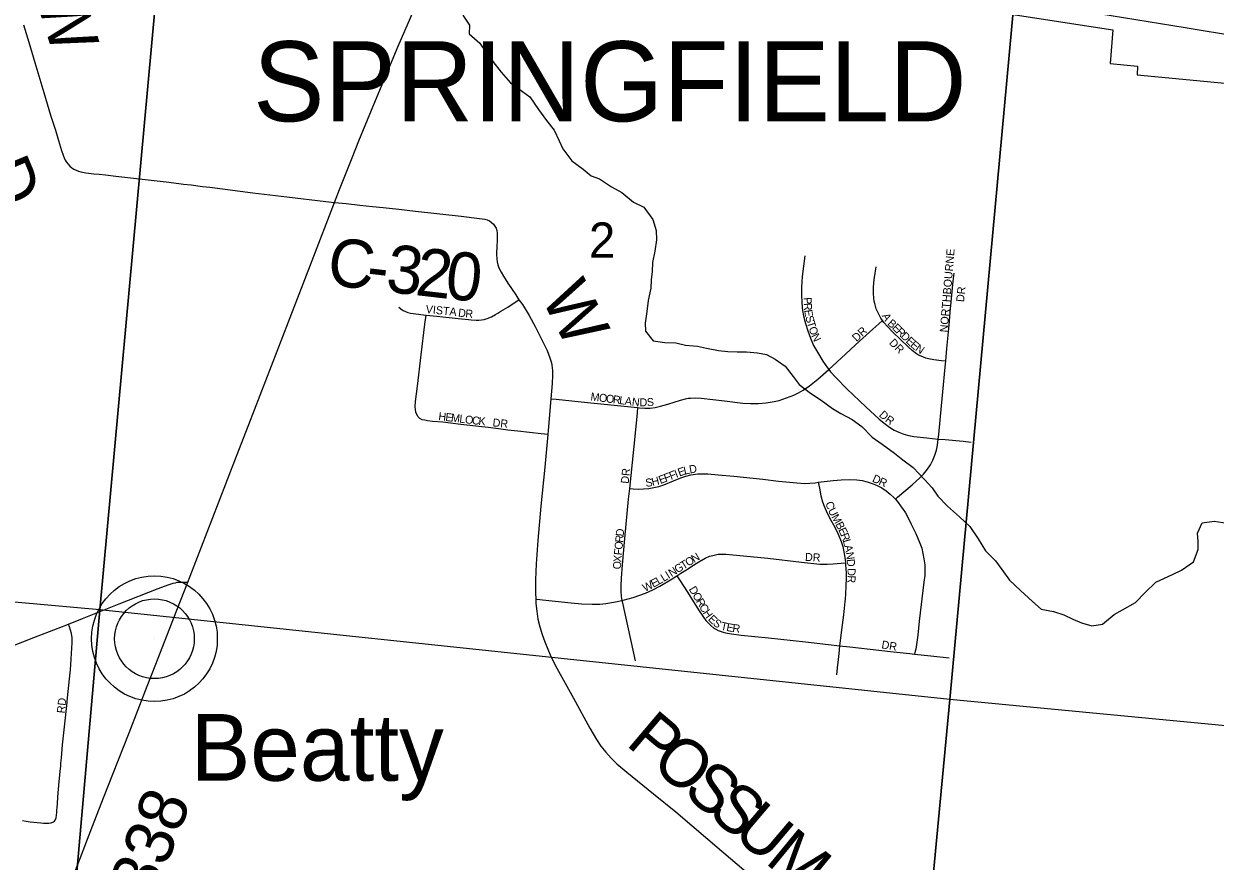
# Model space of a CAD drawing. Extents: x -209 to 4852, y 0 to 905.
# Drawn here: x 81.27 to 109.47, y 211.09 to 230.91 of the extents above; entities that cross this region are included whole.
import ezdxf

# ---------------------------------------------------------------- set-up
doc = ezdxf.new("R2010")
doc.units = 0
for name, color, linetype in [('GM_P_County_Alignment', 7, 'Continuous'), ('GM_X_Corporation_Text', 7, 'Continuous'), ('GM_X_County_Road', 7, 'Continuous'), ('GM_X_County_Road_Text', 7, 'Continuous'), ('GM_X_County_ROW', 7, 'Continuous'), ('GM_X_County_Subdivision', 7, 'Continuous'), ('GM_X_Interstate_Location', 7, 'Continuous'), ('GM_X_Minor_River', 7, 'Continuous'), ('GM_X_Rail_Line_Text', 7, 'Continuous'), ('GM_X_Township_Road', 7, 'Continuous'), ('GM_X_Township_Road_Text', 7, 'Continuous'), ('GM_X_Township_Subdivision_Text', 7, 'Continuous'), ('GM_X_Township_Text', 7, 'Continuous'), ('GM_X_Unincorporated_Location', 7, 'Continuous'), ('GM_X_US_Location', 7, 'Continuous')]:
    doc.layers.add(name, color=color, linetype=linetype)

msp = doc.modelspace()

# ---------------------------------------------------------------- linework, layer by layer
at = {"layer": 'GM_X_County_Road'}
for points in [[(91.656, 231.11), (91.813, 230.874), (91.811, 230.669), (92.059, 230.448), (92.209, 230.227), (92.366, 230.013), (92.568, 229.761), (92.786, 229.51), (92.982, 229.372), (93.245, 229.18), (93.447, 228.883), (93.642, 228.616), (93.822, 228.387), (93.941, 228.136), (94.023, 227.946), (94.24, 227.664), (94.503, 227.465), (94.699, 227.311), (94.895, 227.242), (95.174, 227.05), (95.422, 226.919), (95.7, 226.69), (95.942, 226.567), (96.159, 226.277), (96.233, 226.019), (96.246, 225.799), (96.206, 225.526), (96.151, 225.261), (96.142, 225.049), (96.118, 224.852), (96.109, 224.655), (96.046, 224.359), (96.014, 224.102), (95.974, 223.822), (95.98, 223.632), (96.16, 223.403), (96.44, 223.363), (96.697, 223.354), (96.931, 223.306), (97.211, 223.281), (97.422, 223.234), (97.709, 223.179), (97.929, 223.155), (98.155, 223.145), (98.375, 223.144), (98.632, 223.119), (98.843, 223.08), (99.055, 222.972), (99.288, 222.803), (99.475, 222.559), (99.617, 222.368), (99.888, 222.169), (100.137, 222.001), (100.408, 221.801), (100.603, 221.686), (100.875, 221.54), (101.1, 221.379), (101.348, 221.127), (101.581, 220.958), (101.875, 220.744), (102.071, 220.591), (102.319, 220.407), (102.589, 220.124), (102.769, 219.926), (102.904, 219.727), (103.129, 219.491), (103.415, 219.238), (103.655, 219.009), (103.857, 218.719), (104.029, 218.437), (104.269, 218.2), (104.419, 217.994), (104.599, 217.743), (104.854, 217.498), (105.14, 217.238), (105.35, 217.055), (105.637, 216.999), (105.886, 216.921), (106.097, 216.821), (106.301, 216.729), (106.55, 216.658), (106.8, 216.702), (107.074, 216.927), (107.272, 217.04), (107.576, 217.212), (107.797, 217.445), (108.063, 217.693), (108.458, 217.872), (108.671, 217.976), (108.952, 218.179), (109.06, 218.466), (109.062, 218.656)], [(109.062, 218.656), (109.048, 218.853), (109.156, 219.102), (109.444, 219.138), (109.746, 219.09)]]:
    msp.add_lwpolyline(points, dxfattribs=at)
at = {"layer": 'GM_X_County_Road_Text'}
for points in [[(88.622, 226.679), (88.739, 226.985), (89.036, 227.735), (89.196, 228.14), (89.549, 229.001), (90.127, 230.375), (90.498, 231.229), (90.839, 232.036)], [(85.148, 217.695), (85.202, 217.835), (85.874, 219.572), (86.299, 220.673), (86.59, 221.426), (86.862, 222.119), (87.128, 222.815), (87.535, 223.856), (88.095, 225.304), (88.622, 226.679)], [(88.622, 226.679), (88.898, 226.653), (89.223, 226.618), (89.37, 226.602), (89.521, 226.586), (89.771, 226.559), (90.141, 226.519), (90.538, 226.476), (91.62, 226.352), (92.057, 226.302), (92.178, 226.282), (92.235, 226.265), (92.29, 226.241), (92.339, 226.209), (92.381, 226.169), (92.417, 226.122), (92.444, 226.07), (92.461, 226.013), (92.471, 225.954), (92.473, 225.894), (92.473, 225.772), (92.466, 225.648), (92.459, 225.461), (92.463, 225.335), (92.47, 225.272), (92.487, 225.204), (92.511, 225.136), (92.565, 225.029), (92.618, 224.935), (92.725, 224.772), (92.83, 224.617), (92.914, 224.494), (92.988, 224.379)], [(92.988, 224.379), (93.07, 224.265), (93.133, 224.161), (93.228, 224.004), (93.377, 223.732), (93.547, 223.401), (93.653, 223.177), (93.721, 223.005), (93.755, 222.887), (93.767, 222.828), (93.781, 222.706), (93.782, 222.583), (93.771, 222.398), (93.74, 222.035)], [(93.74, 222.035), (93.676, 221.283), (93.667, 221.187)], [(93.667, 221.187), (93.596, 220.417), (93.505, 219.489), (93.434, 218.683), (93.396, 218.126), (93.38, 217.753), (93.38, 217.441), (93.385, 217.291)], [(80.77, 206.794), (80.798, 206.83), (80.903, 206.982), (80.997, 207.141), (81.082, 207.306), (81.181, 207.532), (81.386, 208.052), (81.809, 209.128), (82.139, 209.965), (82.612, 211.181), (82.879, 211.877), (83.172, 212.629), (83.375, 213.149), (83.761, 214.132), (84.191, 215.23), (84.393, 215.751), (84.821, 216.851), (85.148, 217.695)], [(82.327, 216.704), (82.66, 216.835), (83.527, 217.178), (84.451, 217.547), (84.681, 217.635), (84.799, 217.67), (84.855, 217.682), (84.9, 217.691), (84.942, 217.695), (84.993, 217.695), (85.106, 217.695), (85.148, 217.695)], [(93.385, 217.291), (93.388, 217.191), (93.407, 217.005), (93.437, 216.82), (93.479, 216.637), (93.534, 216.457), (93.597, 216.281), (93.667, 216.107), (93.743, 215.937), (93.886, 215.66), (94.276, 214.952), (94.665, 214.243), (94.824, 213.975), (94.927, 213.817), (95.041, 213.668), (95.167, 213.529), (95.302, 213.399), (95.539, 213.196), (96.168, 212.688), (96.698, 212.256), (97.835, 211.289), (99.258, 210.083)], [(80.282, 215.906), (80.594, 216.03), (80.982, 216.181), (81.505, 216.381), (82.082, 216.608), (82.327, 216.704)]]:
    msp.add_lwpolyline(points, dxfattribs=at)
at = {"layer": 'GM_X_County_ROW'}
msp.add_lwpolyline([(81.259, 230.886), (81.383, 230.469), (81.528, 229.994), (81.744, 229.279), (81.903, 228.743), (82.014, 228.387), (82.088, 228.149), (82.157, 227.911), (82.198, 227.795), (82.221, 227.738), (82.248, 227.684), (82.278, 227.631), (82.314, 227.583), (82.354, 227.539), (82.402, 227.5), (82.45, 227.467), (82.503, 227.44), (82.56, 227.419), (82.618, 227.403), (82.738, 227.381), (82.861, 227.368), (82.924, 227.361), (83.048, 227.347), (83.205, 227.33), (83.445, 227.303), (83.66, 227.279), (83.795, 227.264), (84.211, 227.218), (84.638, 227.168), (84.939, 227.129), (85.05, 227.115), (85.227, 227.093), (85.499, 227.059), (85.667, 227.038), (86.689, 226.91), (87.491, 226.811), (88.417, 226.7), (88.622, 226.679)], dxfattribs=at)
at = {"layer": 'GM_X_County_Subdivision'}
msp.add_line((84.36, 216.356), (84.36, 216.356), dxfattribs=at)
at = {"layer": 'GM_X_Minor_River'}
for points in [[(65.048, 238.898), (84.904, 237.096), (83.068, 217.043), (63.212, 218.824)], [(84.904, 237.096), (105.036, 235.054), (103.184, 214.918), (83.068, 217.043)], [(105.036, 235.054), (125.307, 233.161), (123.431, 212.988), (103.184, 214.918)], [(61.756, 202.559), (81.8, 202.559), (83.068, 217.043), (63.212, 218.824)], [(81.8, 202.559), (102.019, 202.559), (103.184, 214.918), (83.068, 217.043)], [(102.019, 202.559), (122.379, 202.559), (123.431, 212.988), (103.184, 214.918)]]:
    msp.add_lwpolyline(points, close=True, dxfattribs=at)
at = {"layer": 'GM_X_Rail_Line_Text'}
msp.add_lwpolyline([(95.901, 232.909), (99.91, 232.247), (102.8, 231.787), (107, 231.106), (108.753, 230.822), (109.994, 230.618), (112.682, 230.182)], dxfattribs=at)
at = {"layer": 'GM_X_Township_Subdivision_Text'}
for radius in [1.488, 0.943]:
    msp.add_circle((84.36, 216.356), radius, dxfattribs=at)
at = {"layer": 'GM_X_Township_Text'}
for points in [[(99.75, 225.416), (99.692, 224.924), (99.673, 224.676), (99.671, 224.491), (99.681, 224.305), (99.7, 224.12), (99.722, 223.998), (99.768, 223.819), (99.823, 223.642), (99.886, 223.467), (99.962, 223.297), (100.05, 223.134), (100.181, 222.923), (100.286, 222.77), (100.321, 222.726)], [(101.593, 223.885), (101.555, 223.941), (101.495, 224.05), (101.445, 224.165), (101.407, 224.285), (101.393, 224.346), (101.384, 224.408), (101.377, 224.533), (101.38, 224.658), (101.39, 224.783), (101.405, 224.906), (101.445, 225.153)], [(103.087, 222.923), (103.113, 223.225), (103.166, 223.776), (103.194, 224.083), (103.239, 224.575), (103.266, 224.821), (103.286, 225.004)], [(90.144, 224.201), (90.193, 224.161), (90.245, 224.125), (90.301, 224.096), (90.36, 224.075), (90.422, 224.06), (90.484, 224.05), (90.79, 224.016)], [(90.79, 224.016), (91.046, 223.991), (91.552, 223.935), (91.796, 223.909), (91.857, 223.903), (91.973, 223.891), (92.037, 223.893), (92.1, 223.9), (92.16, 223.91), (92.236, 223.934), (92.337, 223.977), (92.428, 224.027), (92.49, 224.063), (92.562, 224.109), (92.72, 224.205), (92.897, 224.324), (92.988, 224.379)], [(93.667, 221.187), (93.511, 221.204), (92.961, 221.265), (92.726, 221.295), (92.501, 221.321), (92.261, 221.351), (92.038, 221.375), (91.611, 221.429), (91.363, 221.456), (91.188, 221.477), (90.942, 221.5), (90.82, 221.516), (90.759, 221.525), (90.698, 221.539), (90.643, 221.567), (90.599, 221.61), (90.566, 221.662), (90.545, 221.72), (90.535, 221.781), (90.532, 221.843), (90.541, 221.966), (90.583, 222.335), (90.675, 223.077), (90.761, 223.798), (90.79, 224.016)], [(100.321, 222.726), (100.51, 222.901), (101.048, 223.396), (101.364, 223.683), (101.501, 223.804), (101.593, 223.885)], [(103.087, 222.923), (102.991, 222.933), (102.804, 222.953), (102.681, 222.977), (102.62, 222.994), (102.561, 223.016), (102.503, 223.04), (102.447, 223.068), (102.394, 223.1), (102.294, 223.177), (102.201, 223.261), (101.839, 223.608), (101.708, 223.742), (101.627, 223.838), (101.593, 223.885)], [(102.909, 221.082), (102.924, 221.187), (102.985, 221.87), (103.033, 222.366), (103.059, 222.613), (103.081, 222.859), (103.087, 222.923)], [(95.795, 221.824), (95.843, 221.819), (95.966, 221.812), (96.09, 221.815), (96.21, 221.829), (96.334, 221.857), (96.512, 221.91), (96.807, 222.005), (96.927, 222.034), (96.989, 222.045), (97.05, 222.051), (97.174, 222.054), (97.298, 222.046), (97.852, 221.982), (98.284, 221.934), (98.469, 221.923), (98.655, 221.925), (98.841, 221.941), (99.024, 221.969), (99.145, 221.997), (99.322, 222.054), (99.495, 222.123), (99.607, 222.177), (99.714, 222.238), (99.867, 222.344), (100.061, 222.499), (100.321, 222.726)], [(100.321, 222.726), (100.363, 222.673), (100.487, 222.535), (100.749, 222.271), (101.196, 221.841), (101.516, 221.548), (101.66, 221.43), (101.761, 221.359), (101.867, 221.295), (101.978, 221.24), (102.095, 221.198), (102.214, 221.165), (102.336, 221.141), (102.643, 221.106), (102.909, 221.082)], [(93.74, 222.035), (93.868, 222.021), (94.608, 221.942), (95.795, 221.824)], [(95.795, 221.824), (95.784, 221.704), (95.727, 221.143), (95.667, 220.525), (95.602, 219.911)], [(101.903, 219.657), (101.949, 219.706), (102.294, 219.996), (102.477, 220.167), (102.564, 220.251), (102.659, 220.368), (102.728, 220.471), (102.786, 220.581), (102.832, 220.697), (102.866, 220.817), (102.89, 220.94), (102.909, 221.082)], [(102.909, 221.082), (103.074, 221.067), (103.504, 221.028), (103.688, 221.006)], [(95.602, 219.911), (95.687, 219.906), (95.811, 219.898), (95.935, 219.899), (96.06, 219.91), (96.182, 219.931), (96.301, 219.962), (96.417, 219.999), (96.644, 220.094), (96.816, 220.166), (96.935, 220.206), (97.055, 220.233), (97.169, 220.251), (97.219, 220.256), (97.335, 220.26), (97.456, 220.256), (97.705, 220.237), (98.076, 220.2), (98.757, 220.129), (99.128, 220.088), (99.561, 220.043), (99.747, 220.033), (99.871, 220.036), (99.995, 220.047), (100.071, 220.057)], [(100.071, 220.057), (100.427, 220.103), (100.613, 220.117), (100.8, 220.12), (100.986, 220.113), (101.11, 220.097), (101.231, 220.071), (101.349, 220.032), (101.464, 219.983), (101.573, 219.924), (101.676, 219.855), (101.772, 219.775), (101.856, 219.701), (101.903, 219.657)], [(100.071, 220.057), (100.097, 219.918), (100.134, 219.734), (100.174, 219.595), (100.212, 219.494), (100.258, 219.379), (100.303, 219.282), (100.369, 219.16), (100.462, 218.999), (100.544, 218.83), (100.614, 218.657), (100.651, 218.537), (100.678, 218.415), (100.705, 218.23), (100.714, 218.154)], [(95.602, 219.911), (95.575, 219.656), (95.488, 218.725), (95.431, 218.102), (95.407, 217.791), (95.397, 217.606), (95.396, 217.481), (95.406, 217.357), (95.422, 217.259)], [(101.903, 219.657), (101.961, 219.582), (102.021, 219.498), (102.081, 219.416), (102.135, 219.332), (102.172, 219.266), (102.268, 219.067), (102.377, 218.843), (102.477, 218.615), (102.52, 218.498), (102.55, 218.372), (102.573, 218.244), (102.59, 218.102), (102.593, 217.988), (102.59, 217.854), (102.57, 217.695), (102.459, 216.775), (102.425, 216.439), (102.397, 216.216), (102.387, 216.162), (102.378, 216.111), (102.365, 216.062), (102.348, 215.993)], [(96.721, 217.845), (96.82, 217.908), (96.934, 217.981), (97.119, 218.099), (97.244, 218.179), (97.397, 218.265), (97.499, 218.309), (97.579, 218.329), (97.639, 218.344), (97.701, 218.353), (97.762, 218.359), (97.886, 218.359), (98.133, 218.337), (98.874, 218.262), (99.675, 218.17), (100.107, 218.124), (100.279, 218.121), (100.426, 218.125), (100.611, 218.144), (100.714, 218.154)], [(100.714, 218.154), (100.719, 218.106), (100.733, 217.919), (100.735, 217.794), (100.715, 217.42), (100.705, 217.295), (100.699, 217.233), (100.666, 216.925), (100.653, 216.802), (100.633, 216.618), (100.575, 216.191)], [(95.422, 217.259), (95.454, 217.266), (95.693, 217.333), (95.985, 217.436), (96.155, 217.511), (96.32, 217.598), (96.612, 217.777), (96.721, 217.845)], [(96.721, 217.845), (96.799, 217.723), (96.973, 217.455), (97.233, 217.04), (97.339, 216.886), (97.414, 216.791), (97.466, 216.731), (97.528, 216.672), (97.601, 216.609), (97.645, 216.58), (97.699, 216.55), (97.753, 216.531), (97.818, 216.509), (97.878, 216.493), (98.016, 216.471), (98.244, 216.441), (98.894, 216.374), (99.767, 216.282), (100.314, 216.219), (100.575, 216.191)], [(93.385, 217.291), (93.483, 217.283), (93.545, 217.277), (94.224, 217.203), (94.471, 217.181), (94.719, 217.171), (94.9, 217.174), (95.047, 217.187), (95.272, 217.226), (95.422, 217.259)], [(95.422, 217.259), (95.427, 217.234), (95.697, 216.016), (95.738, 215.834)], [(81.233, 212.054), (81.324, 212.04), (81.415, 212.025), (81.668, 212.001), (81.73, 211.995), (81.792, 211.993), (81.856, 211.994), (81.916, 212.003), (81.968, 212.023), (81.991, 212.04), (82.011, 212.066), (82.032, 212.12), (82.042, 212.181), (82.049, 212.242), (82.052, 212.298), (82.057, 212.362), (82.062, 212.446), (82.076, 212.611), (82.106, 212.98), (82.136, 213.285), (82.141, 213.341), (82.147, 213.41), (82.15, 213.471), (82.158, 213.534), (82.186, 213.844), (82.237, 214.34), (82.284, 214.774), (82.305, 214.96), (82.348, 215.404), (82.37, 215.623), (82.379, 215.743), (82.389, 215.879), (82.397, 216.009), (82.406, 216.133), (82.414, 216.258), (82.409, 216.373), (82.394, 216.479), (82.348, 216.637), (82.327, 216.704)], [(100.575, 216.191), (100.555, 216.003), (100.542, 215.867), (100.52, 215.664), (100.502, 215.502)], [(100.575, 216.191), (100.821, 216.162), (101.506, 216.089), (101.853, 216.049), (102.241, 216.005), (102.348, 215.993)], [(102.348, 215.993), (102.735, 215.949), (103.168, 215.903)]]:
    msp.add_lwpolyline(points, dxfattribs=at)
at = {"layer": 'GM_X_US_Location'}
msp.add_lwpolyline([(95.856, 232.496), (107.042, 230.768), (106.984, 229.969), (107.626, 229.905), (107.622, 229.697), (114.33, 229.064), (114.15, 226.117), (113.295, 226.201), (113.236, 225.433), (114.413, 225.335), (114.471, 226.021), (114.462, 226.059), (114.454, 226.105), (114.45, 226.148), (114.452, 226.194), (114.464, 226.417), (114.481, 226.713), (114.529, 227.378), (114.538, 227.47), (114.71, 229.317), (112.595, 229.626), (112.848, 231.437)], dxfattribs=at)

# ---------------------------------------------------------------- texts
at = {"layer": 'GM_P_County_Alignment'}
for s, height, rotation, p in [('C', 1.136, 353.2913, (88.418, 224.736)), ('3', 1.136, 353.3432, (89.81, 224.572)), ('2', 1.136, 353.4658, (90.508, 224.491)), ('0', 1.136, 353.8878, (91.212, 224.41)), ('-', 1.136, 353.3006, (89.345, 224.627)), ('W', 1.136, 297.3396, (93.493, 224.447)), ('P', 1.136, 319.7108, (95.49, 213.855)), ('O', 1.136, 319.7114, (96.075, 213.359)), ('S', 1.136, 319.709, (96.838, 212.713)), ('S', 1.136, 319.7098, (97.423, 212.217)), ('C-338', 1.1364, 68.9618, (83.748, 208.646)), ('U', 1.136, 319.714, (98.008, 211.721)), ('M', 1.136, 320.5724, (98.785, 211.063))]:
    msp.add_text(s, height=height, rotation=rotation, dxfattribs=at).set_placement(p)
at = {"layer": 'GM_X_Corporation_Text'}
msp.add_text('SPRINGFIELD', height=1.89394, rotation=0, dxfattribs=at).set_placement((86.694, 228.6))
at = {"layer": 'GM_X_Interstate_Location'}
for s, height, rotation, p in [('NORTHBOURNE', 0.18939, 85.1899, (103.133, 223.599)), ('DR', 0.1894, 83.994, (103.52, 224.316)), ('VISTA', 0.1894, 354.4288, (90.774, 224.065)), ('P', 0.189, 273.1707, (99.721, 224.431)), ('R', 0.189, 273.1879, (99.728, 224.298)), ('D', 0.189, 353.241, (91.54, 223.982)), ('R', 0.189, 355.4816, (91.713, 223.961)), ('E', 0.189, 278.3573, (99.738, 224.13)), ('S', 0.189, 285.6834, (99.763, 223.972)), ('T', 0.189, 286.2382, (99.8, 223.842)), ('A', 0.189, 298.3052, (101.572, 223.999)), ('B', 0.189, 317.9267, (101.694, 223.797)), ('O', 0.189, 288.5803, (99.84, 223.706)), ('DR', 0.1894, 42.8801, (100.978, 223.372)), ('E', 0.189, 315.9854, (101.804, 223.698)), ('R', 0.189, 315.979, (101.9, 223.605)), ('D', 0.189, 315.9815, (102.008, 223.501)), ('N', 0.189, 294.5282, (99.901, 223.528)), ('DR', 0.1894, 315, (101.733, 223.344)), ('E', 0.189, 316.1475, (102.128, 223.385)), ('E', 0.189, 319.6013, (102.234, 223.284)), ('N', 0.189, 325.2101, (102.351, 223.185)), ('M', 0.189, 352.7123, (94.673, 221.998)), ('O', 0.189, 352.723, (94.872, 221.973)), ('O', 0.189, 352.7123, (95.037, 221.952)), ('R', 0.189, 352.7183, (95.202, 221.931)), ('L', 0.189, 352.7123, (95.351, 221.912)), ('A', 0.189, 352.723, (95.483, 221.895)), ('N', 0.189, 353.7626, (95.652, 221.873)), ('D', 0.189, 0.8261, (95.843, 221.854)), ('S', 0.189, 3.3359, (96.019, 221.857)), ('H', 0.189, 353.1325, (91.073, 221.532)), ('E', 0.189, 353.1258, (91.238, 221.512)), ('M', 0.189, 353.1268, (91.371, 221.496)), ('L', 0.189, 353.1274, (91.569, 221.472)), ('O', 0.189, 353.1306, (91.702, 221.456)), ('D', 0.189, 316.7081, (101.495, 221.637)), ('R', 0.189, 324.8645, (101.639, 221.504)), ('C', 0.189, 353.3694, (91.868, 221.436)), ('K', 0.189, 354.7503, (92.022, 221.418)), ('DR', 0.1894, 353.988, (92.356, 221.382)), ('DR', 0.1894, 83.9826, (95.583, 220.017)), ('E', 0.189, 20.7973, (96.335, 220.016)), ('F', 0.189, 21.4548, (96.461, 220.064)), ('F', 0.189, 21.4548, (96.586, 220.113)), ('I', 0.189, 21.4577, (96.71, 220.162)), ('E', 0.189, 20.1372, (96.786, 220.192)), ('L', 0.189, 12.797, (96.905, 220.236)), ('D', 0.189, 10.1055, (97.033, 220.265)), ('D', 0.189, 335.7035, (101.333, 220.079)), ('S', 0.189, 6.7354, (95.991, 219.949)), ('H', 0.189, 13.6626, (96.148, 219.969)), ('R', 0.189, 336.2578, (101.486, 220.01)), ('C', 0.189, 286.9795, (100.237, 219.571)), ('U', 0.189, 296.7336, (100.294, 219.395)), ('M', 0.189, 299.3277, (100.373, 219.238)), ('B', 0.189, 297.9282, (100.47, 219.064)), ('D', 0.189, 84.5058, (95.464, 218.772)), ('E', 0.189, 295.0804, (100.54, 218.934)), ('R', 0.189, 291.2197, (100.595, 218.816)), ('O', 0.189, 84.5249, (95.434, 218.457)), ('R', 0.189, 84.5274, (95.45, 218.623)), ('L', 0.189, 286.1968, (100.648, 218.681)), ('A', 0.189, 282.9389, (100.684, 218.555)), ('X', 0.189, 84.9006, (95.407, 218.158)), ('F', 0.189, 84.5001, (95.421, 218.324)), ('O', 0.189, 31.9923, (96.993, 218.059)), ('N', 0.189, 31.0462, (97.133, 218.147)), ('DR', 0.1894, 356.9833, (99.754, 218.199)), ('N', 0.189, 277.8272, (100.721, 218.397)), ('O', 0.189, 87.5513, (95.4, 217.994)), ('N', 0.189, 31.9923, (96.597, 217.812)), ('G', 0.189, 31.9984, (96.738, 217.9)), ('T', 0.189, 31.9735, (96.879, 217.989)), ('D', 0.189, 275.6486, (100.743, 218.234)), ('D', 0.189, 271.3554, (100.763, 218.022)), ('W', 0.189, 26.6478, (95.969, 217.462)), ('E', 0.189, 27.3327, (96.165, 217.56)), ('L', 0.189, 30.6914, (96.294, 217.627)), ('L', 0.189, 31.9228, (96.413, 217.697)), ('I', 0.189, 31.9806, (96.526, 217.768)), ('R', 0.189, 268.1297, (100.767, 217.858)), ('D', 0.189, 300.3115, (97, 217.53)), ('O', 0.189, 300.3115, (97.084, 217.386)), ('R', 0.189, 300.2932, (97.168, 217.242)), ('C', 0.189, 300.3283, (97.244, 217.113)), ('H', 0.189, 305.2942, (97.329, 216.968)), ('E', 0.189, 315.6689, (97.45, 216.804)), ('S', 0.189, 321.6903, (97.561, 216.696)), ('T', 0.189, 347.6248, (97.75, 216.574)), ('E', 0.189, 349.3441, (97.886, 216.544)), ('R', 0.189, 353.4215, (98.032, 216.517)), ('DR', 0.1894, 350.5377, (101.558, 216.131)), ('RD', 0.1894, 83.994, (82.235, 214.583))]:
    msp.add_text(s, height=height, rotation=rotation, dxfattribs=at).set_placement(p)
at = {"layer": 'GM_X_Township_Road'}
for s, rotation, p in [('W', 287.5243, (81.545, 231.498)), ('D', 292.6768, (80.254, 227.471))]:
    msp.add_text(s, height=1.136, rotation=rotation, dxfattribs=at).set_placement(p)
at = {"layer": 'GM_X_Township_Road_Text'}
msp.add_text('2', height=0.837, rotation=0, dxfattribs=at).set_placement((94.644, 225.37))
at = {"layer": 'GM_X_Unincorporated_Location'}
msp.add_text('Beatty', height=1.5795, rotation=0, dxfattribs=at).set_placement((85.219, 212.995))

doc.saveas('drawing.dxf')
